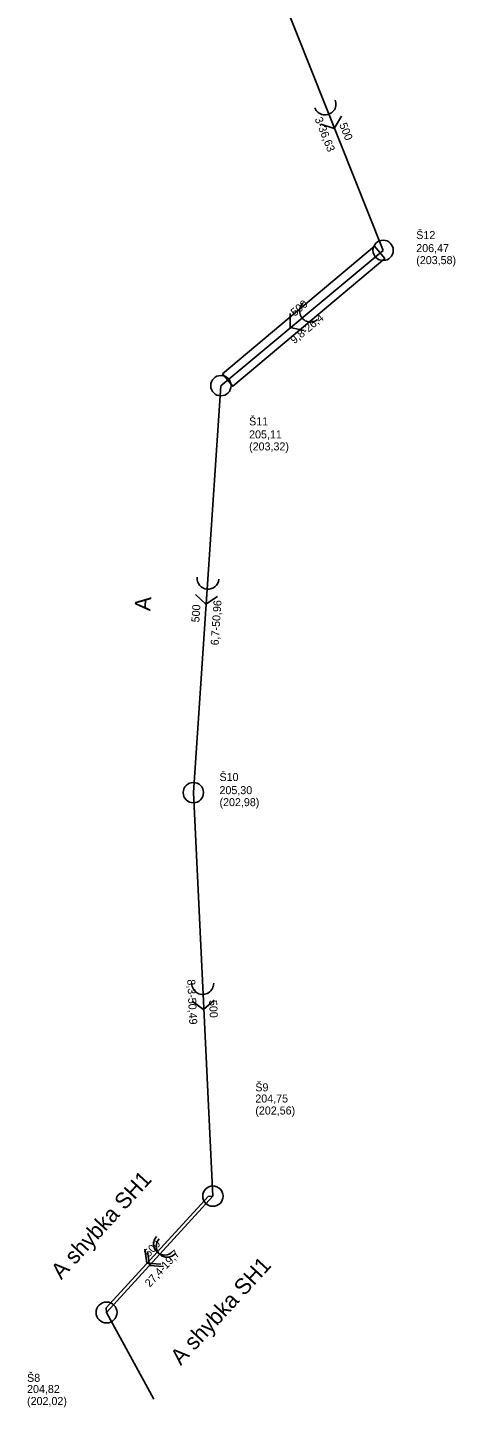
# Model space of a CAD drawing. Extents: x -569540 to -569072, y -1179643 to -1178245.
# Drawn here: x -569533 to -569479.5, y -1179643.3 to -1179470.9 of the extents above; entities that cross this region are included whole.
import ezdxf

# ---------------------------------------------------------------- set-up
doc = ezdxf.new("R2010")
doc.units = 0
for name, color, linetype in [('Vrstva 1', 7, 'Continuous'), ('Vrstva 15', 7, 'Continuous'), ('Vrstva 27', 7, 'Continuous'), ('Vrstva 29', 7, 'Continuous'), ('Vrstva 35', 7, 'Continuous'), ('Vrstva 41', 7, 'Continuous'), ('Vrstva 44', 7, 'Continuous'), ('Vrstva 45', 7, 'Continuous'), ('Vrstva 56', 7, 'Continuous'), ('Vrstva 57', 7, 'Continuous')]:
    doc.layers.add(name, color=color, linetype=linetype)

# ---------------------------------------------------------------- blocks, each defined once
blk = doc.blocks.new('100')
at = {"layer": 'Vrstva 1'}
blk.add_circle((0, 0), 1.27, dxfattribs=at)
blk = doc.blocks.new('86')
at = {"layer": 'Vrstva 1'}
blk.add_lwpolyline([(0.79, 1.37), (1.89, 0), (0.79, -1.38)], dxfattribs=at)
blk.add_arc((-1.37, 0), 1.37, 270, 90, dxfattribs=at)

msp = doc.modelspace()

# ---------------------------------------------------------------- linework, layer by layer
at = {"layer": 'Vrstva 15'}
for p, q in [((-569502.06, -1179464.71), (-569488.5, -1179498.74)), ((-569488.5, -1179498.74), (-569508.78, -1179515.65)), ((-569508.78, -1179515.65), (-569512.23, -1179566.5)), ((-569512.23, -1179566.5), (-569509.78, -1179616.92)), ((-569509.78, -1179616.92), (-569523.08, -1179631.46)), ((-569523.08, -1179631.46), (-569517.18, -1179642.29))]:
    msp.add_line(p, q, dxfattribs=at)
msp.add_lwpolyline([(-569509.78, -1179616.92), (-569510.39, -1179616.95), (-569523.13, -1179630.87), (-569523.08, -1179631.46)], dxfattribs=at)
at = {"layer": 'Vrstva 27'}
msp.add_lwpolyline([(-569508.59, -1179514.19), (-569489.58, -1179498.22), (-569488.29, -1179499.75), (-569507.31, -1179515.73), (-569508.59, -1179514.19)], dxfattribs=at)

# ---------------------------------------------------------------- block references
at = {"layer": 'Vrstva 29'}
for p, xscale, yscale, rotation in [((-569488.5, -1179498.74), 0.999999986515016, 0.9999999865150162, -105.00000012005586), ((-569508.78, -1179515.65), 0.9999999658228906, 0.9999999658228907, -117.99999982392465), ((-569512.23, -1179566.5), 0.9999999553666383, 0.9999999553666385, 88.99999999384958), ((-569509.78, -1179616.92), 0.9999999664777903, 0.9999999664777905, -132.99999806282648), ((-569523.08, -1179631.46), 1.0316957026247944, 1.0316957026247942, 156.4154111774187)]:
    msp.add_blockref('100', p, dxfattribs=dict(at, xscale=xscale, yscale=yscale, rotation=rotation))
at = {"layer": 'Vrstva 41'}
for p, xscale, yscale, rotation in [((-569495.28, -1179481.73), 0.999999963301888, 0.9999999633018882, -69.00000101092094), ((-569498.64, -1179507.19), 0.9999999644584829, 0.999999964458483, -140.99999893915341), ((-569510.51, -1179541.07), 0.9999999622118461, 0.999999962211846, -94.99999985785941), ((-569511.01, -1179591.71), 0.9999999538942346, 0.9999999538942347, -87.9999999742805), ((-569516.76, -1179623.91), 0.9999999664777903, 0.9999999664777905, -132.99999806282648), ((-569516.43, -1179624.19), 0.9999999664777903, 0.9999999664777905, -132.99999806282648)]:
    msp.add_blockref('86', p, dxfattribs=dict(at, xscale=xscale, yscale=yscale, rotation=rotation))

# ---------------------------------------------------------------- texts
at = {"layer": 'Vrstva 35'}
for s, rotation, p in [('A', 86.11, (-569517.61, -1179543.85)), ('A shybka SH1', 47.55, (-569528.75, -1179627.43)), ('A shybka SH1', 47.54, (-569513.81, -1179638.16))]:
    msp.add_text(s, height=2, rotation=rotation, dxfattribs=at).set_placement(p)
at = {"layer": 'Vrstva 44'}
for rotation, p in [(291.72, (-569494.01, -1179483.03)), (39.83, (-569499.54, -1179507.04)), (86.11, (-569511.49, -1179545.25)), (272.78, (-569510.27, -1179592.43)), (47.55, (-569517.77, -1179624.61))]:
    msp.add_text('500', height=1, rotation=rotation, dxfattribs=at).set_placement(p)
at = {"layer": 'Vrstva 45'}
for s, rotation, p in [('3-36,63', 291.72, (-569497.08, -1179482.32)), ('9,8-26,4', 39.83, (-569499.6, -1179510.48)), ('6,7-50,96', 86.11, (-569509.08, -1179548.12)), ('8,3-50,49', 272.78, (-569513, -1179589.85)), ('27,4-19,7', 47.55, (-569517.67, -1179628.36))]:
    msp.add_text(s, height=1, rotation=rotation, dxfattribs=at).set_placement(p)
at = {"layer": 'Vrstva 56'}
for s, p in [('206,47 ', (-569484.36, -1179498.96)), ('(203,58)', (-569484.36, -1179500.46)), ('205,11 ', (-569505.26, -1179522.24)), ('(203,32)', (-569505.26, -1179523.74)), ('205,30 ', (-569508.96, -1179566.69)), ('(202,98)', (-569508.96, -1179568.19)), ('204,75 ', (-569504.48, -1179605.22)), ('(202,56)', (-569504.48, -1179606.72)), ('204,82 ', (-569533.02, -1179641.52)), ('(202,02)', (-569533.02, -1179643.02))]:
    msp.add_text(s, height=1, dxfattribs=at).set_placement(p)
at = {"layer": 'Vrstva 57'}
for s, p in [('Š12', (-569484.36, -1179497.33)), ('Š11', (-569505.26, -1179520.61)), ('Š10', (-569508.96, -1179565.05)), ('Š9', (-569504.48, -1179603.82)), ('Š8', (-569533.02, -1179640.12))]:
    msp.add_text(s, height=1, dxfattribs=at).set_placement(p)

doc.saveas('drawing.dxf')
